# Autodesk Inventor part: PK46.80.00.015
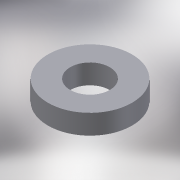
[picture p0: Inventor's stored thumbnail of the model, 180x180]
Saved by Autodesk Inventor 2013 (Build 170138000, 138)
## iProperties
Shininess: 64.0
Length Units: 11269
Angle Units: 11279
Time Units: 11290
Mass Units: 11283
Length Display Precision: 3
Angle Display Precision: 2
Compacted: True
Part Number: PK46.80.00.015
Document SubType Name: Modeling
Created: 2005-01
Material: Steel, Mild
Designer: SAlex
Manufacturer: Standard
Standards Organization: Custom
Density: 7.86 g/cm^3
Mass: 5555.91 g
Surface Area: 667.588 cm^2
Volume: 706.858 cm^3
Density: 0.0
Volumn: 0.0
Area: 0.0
PropertySet Name: Model Information
Control State: 0
Master: False
Checked Out: False
Checked Out Date: 2008-10-15
Last Check In Date: 2008-10-15
Author: SAlex
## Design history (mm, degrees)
sketch "Sketch1"
  geometry: C1 r 40 at (0, 0); C2 r 85 at (0, 0)
  constraints: 2 centre point, 1 coincident, 1 other
  dimensions: "d0" = 80 diameter of C1; "d1" = 170 diameter of C2
extrude "Extrusion1" new body sketch "Sketch1" distance "d2" = 40; taper "d3" = 0 deg
body "Solid1"
